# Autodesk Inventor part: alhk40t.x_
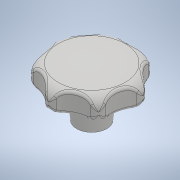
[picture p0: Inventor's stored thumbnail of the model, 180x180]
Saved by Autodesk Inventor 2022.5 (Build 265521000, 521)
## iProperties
Part Number: alhk40t.x_
Material: 一般
Document SubType Name: Modeling
Designer: ImaoCorp
Density: 1 g/cm^3
Appearance: 既定
Sending System: SOLIDWORKS 2017-2017317
MC: AMD64
MC_MODEL: Intel64 Family 6 Model 60 Stepping 3, GenuineIntel
OS: Windows_NT
FRU: Parasolid Version 29.0, build 201,  4-17-2017
FORMAT: text
GUISE: transmit
KEY: alhk40t
FILE: alhk40t.x_t
DATE: Tue Feb 05 16:18:39 2019
Author: ImaoCorp
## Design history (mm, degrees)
feature "Base1"
node "ソリッド1"
